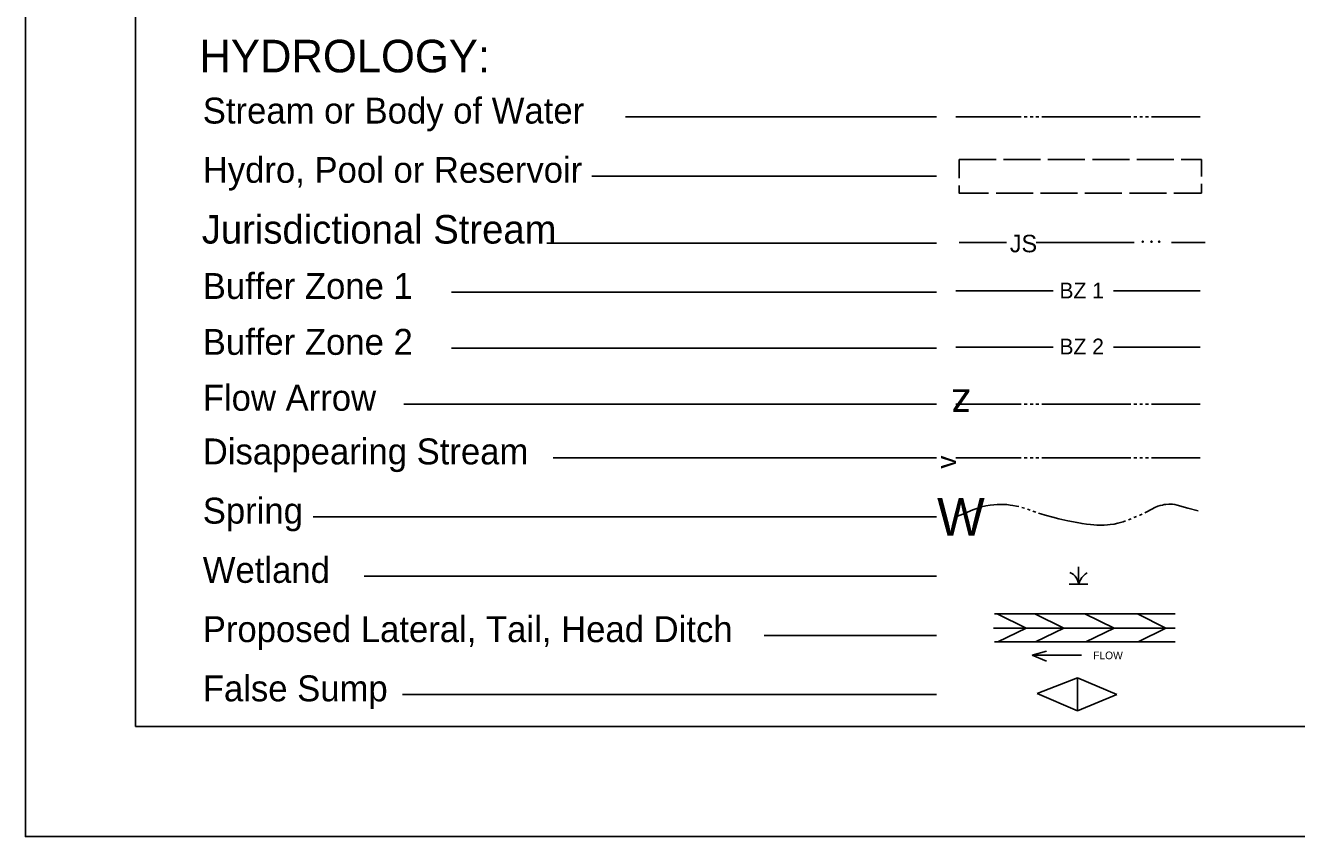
# Model space of a CAD drawing. Extents: x 1855058 to 1858918, y 1540202 to 1542502.
# Drawn here: x 1857118.6 to 1857551.6, y 1541401.8 to 1541678.1 of the extents above; entities that cross this region are included whole.
import ezdxf

# ---------------------------------------------------------------- set-up
doc = ezdxf.new("R2010")
doc.units = 0
for name, color, linetype in [('Default', 7, 'Continuous'), ('Exist Contamination Potential Cell', 7, 'Continuous'), ('Sheet Data Field CELL', 7, 'Continuous'), ('Sheet Symbology CELL', 7, 'Continuous')]:
    doc.layers.add(name, color=color, linetype=linetype)

msp = doc.modelspace()

# ---------------------------------------------------------------- linework, layer by layer
at = {"layer": 'Default'}
msp.add_lwpolyline([(1857118.6, 1542501.77), (1857118.6, 1541401.77), (1858818.6, 1541401.77), (1858818.6, 1542501.77)], close=True, dxfattribs=at)
at = {"layer": 'Exist Contamination Potential Cell'}
for p, q in [((1857118.6, 1542501.77), (1857118.6, 1541401.77)), ((1857118.6, 1541401.77), (1858818.6, 1541401.77))]:
    msp.add_line(p, q, dxfattribs=at)
at = {"layer": 'Sheet Data Field CELL'}
for p, q in [((1857428.97, 1541646.94), (1857323.03, 1541646.94)), ((1857435.54, 1541646.94), (1857457.76, 1541646.94)), ((1857458.77, 1541646.94), (1857459.78, 1541646.94)), ((1857460.78, 1541646.94), (1857461.79, 1541646.94)), ((1857462.8, 1541646.94), (1857463.81, 1541646.94)), ((1857464.82, 1541646.94), (1857495.09, 1541646.94)), ((1857496.1, 1541646.94), (1857497.11, 1541646.94)), ((1857498.12, 1541646.94), (1857499.12, 1541646.94)), ((1857500.13, 1541646.94), (1857501.14, 1541646.94)), ((1857502.15, 1541646.94), (1857518.77, 1541646.94)), ((1857436.61, 1541632.39), (1857449.22, 1541632.39)), ((1857436.61, 1541626.03), (1857436.61, 1541632.39)), ((1857451.74, 1541632.39), (1857464.35, 1541632.39)), ((1857466.88, 1541632.39), (1857479.49, 1541632.39)), ((1857482.01, 1541632.39), (1857494.62, 1541632.39)), ((1857497.14, 1541632.39), (1857509.76, 1541632.39)), ((1857428.97, 1541626.76), (1857311.54, 1541626.76)), ((1857461.81, 1541620.96), (1857449.19, 1541620.96)), ((1857476.94, 1541620.96), (1857464.33, 1541620.96)), ((1857492.07, 1541620.96), (1857479.46, 1541620.96)), ((1857507.21, 1541620.96), (1857494.6, 1541620.96)), ((1857428.97, 1541603.96), (1857296.18, 1541603.96)), ((1857428.97, 1541587.2), (1857263.75, 1541587.2)), ((1857435.54, 1541587.64), (1857468.62, 1541587.64)), ((1857518.77, 1541587.64), (1857489.21, 1541587.64)), ((1857428.97, 1541568.16), (1857263.75, 1541568.16)), ((1857435.54, 1541568.49), (1857468.62, 1541568.49)), ((1857518.77, 1541568.49), (1857489.21, 1541568.49)), ((1857428.97, 1541549.12), (1857247.52, 1541549.12)), ((1857435.54, 1541549.12), (1857457.76, 1541549.12)), ((1857458.77, 1541549.12), (1857459.78, 1541549.12)), ((1857460.78, 1541549.12), (1857461.79, 1541549.12)), ((1857462.8, 1541549.12), (1857463.81, 1541549.12)), ((1857464.82, 1541549.12), (1857495.09, 1541549.12)), ((1857496.1, 1541549.12), (1857497.11, 1541549.12)), ((1857498.12, 1541549.12), (1857499.12, 1541549.12)), ((1857500.13, 1541549.12), (1857501.14, 1541549.12)), ((1857502.15, 1541549.12), (1857518.77, 1541549.12)), ((1857428.97, 1541530.84), (1857298.3, 1541530.84)), ((1857435.54, 1541530.84), (1857457.76, 1541530.84)), ((1857458.77, 1541530.84), (1857459.78, 1541530.84)), ((1857460.78, 1541530.84), (1857461.79, 1541530.84)), ((1857462.8, 1541530.84), (1857463.81, 1541530.84)), ((1857464.82, 1541530.84), (1857495.09, 1541530.84)), ((1857496.1, 1541530.84), (1857497.11, 1541530.84)), ((1857498.12, 1541530.84), (1857499.12, 1541530.84)), ((1857500.13, 1541530.84), (1857501.14, 1541530.84)), ((1857502.15, 1541530.84), (1857518.77, 1541530.84)), ((1857428.97, 1541510.66), (1857216.61, 1541510.66)), ((1857461.78, 1541512.63), (1857462.74, 1541512.3)), ((1857494.27, 1541509.68), (1857495.2, 1541510.06)), ((1857496.15, 1541510.42), (1857497.07, 1541510.81)), ((1857477.27, 1541487.75), (1857477.27, 1541493.67)), ((1857428.97, 1541490.48), (1857234.03, 1541490.48)), ((1857474.08, 1541487.75), (1857480.51, 1541487.75)), ((1857448.63, 1541477.62), (1857510.18, 1541477.62)), ((1857449.54, 1541477.62), (1857459.41, 1541472.78)), ((1857462.36, 1541477.62), (1857472.24, 1541472.78)), ((1857479.46, 1541477.62), (1857489.38, 1541472.78)), ((1857497.36, 1541477.62), (1857507.04, 1541472.78)), ((1857428.97, 1541470.31), (1857370.27, 1541470.31)), ((1857448.36, 1541472.78), (1857510.18, 1541472.78)), ((1857459.41, 1541472.78), (1857449.81, 1541468.09)), ((1857472.24, 1541472.78), (1857462.68, 1541468.09)), ((1857489.38, 1541472.78), (1857479.82, 1541468.09)), ((1857507.04, 1541472.78), (1857497.62, 1541468.09)), ((1857448.63, 1541468.09), (1857510.18, 1541468.09)), ((1857461.49, 1541463.55), (1857466.33, 1541464.91)), ((1857461.49, 1541463.55), (1857478.29, 1541463.55)), ((1857461.49, 1541463.55), (1857466.33, 1541461.58)), ((1857476.94, 1541455.79), (1857463.24, 1541450.47)), ((1857476.94, 1541444.64), (1857476.94, 1541455.79)), ((1857490.37, 1541450.21), (1857476.94, 1541455.79)), ((1857428.97, 1541450.13), (1857247.08, 1541450.13)), ((1857463.24, 1541450.47), (1857476.94, 1541444.64)), ((1857476.94, 1541444.64), (1857490.37, 1541450.21))]:
    msp.add_line(p, q, dxfattribs=at)
for points in [[(1857512.28, 1541632.39), (1857519.16, 1541632.39), (1857519.16, 1541626.66)], [(1857446.67, 1541620.96), (1857436.61, 1541620.96), (1857436.61, 1541623.51)], [(1857519.16, 1541624.14), (1857519.16, 1541620.96), (1857509.73, 1541620.96)], [(1857436.61, 1541604.16), (1857452.76, 1541604.16)], [(1857462.89, 1541604.16), (1857477.03, 1541604.16)], [(1857477.03, 1541604.16), (1857496.2, 1541604.16)], [(1857508.91, 1541604.16), (1857520.43, 1541604.16)], [(1857435.55, 1541510.66), (1857438.41, 1541511.86), (1857441.29, 1541513.07), (1857442.01, 1541513.35), (1857443.28, 1541513.79), (1857444.26, 1541514.06), (1857445.74, 1541514.4), (1857447.23, 1541514.66), (1857448.48, 1541514.81), (1857449.59, 1541514.9), (1857450.56, 1541514.93), (1857451.41, 1541514.93), (1857452.91, 1541514.84), (1857454.04, 1541514.72), (1857454.87, 1541514.6), (1857456.12, 1541514.36), (1857456.98, 1541514.16)], [(1857457.96, 1541513.89), (1857458.43, 1541513.75), (1857458.92, 1541513.6)], [(1857459.88, 1541513.29), (1857460.29, 1541513.15), (1857460.84, 1541512.96)], [(1857499.83, 1541512.08), (1857500.31, 1541512.31), (1857502.29, 1541513.35), (1857503.3, 1541513.84), (1857504.35, 1541514.27), (1857505.14, 1541514.53), (1857505.85, 1541514.71), (1857506.48, 1541514.84), (1857507.03, 1541514.93), (1857508.02, 1541514.99), (1857508.75, 1541514.99), (1857509.29, 1541514.95), (1857510.1, 1541514.84), (1857510.89, 1541514.66), (1857514.47, 1541513.68), (1857518.04, 1541512.68)], [(1857463.7, 1541511.97), (1857464.47, 1541511.71), (1857465.88, 1541511.29), (1857468.59, 1541510.57), (1857470.63, 1541510.06), (1857473.7, 1541509.35), (1857476.79, 1541508.71), (1857478.5, 1541508.41), (1857480.02, 1541508.18), (1857481.35, 1541508.03), (1857482.53, 1541507.93), (1857483.55, 1541507.88), (1857484.46, 1541507.85), (1857486.02, 1541507.88), (1857487.19, 1541507.95), (1857488.08, 1541508.05), (1857489.38, 1541508.24), (1857490.66, 1541508.52), (1857491.63, 1541508.78), (1857492.48, 1541509.04), (1857493.32, 1541509.34)], [(1857498, 1541511.21), (1857498.2, 1541511.29), (1857498.92, 1541511.62)], [(1857477.27, 1541487.75), (1857477.12, 1541488.46), (1857476.91, 1541489.17), (1857476.56, 1541489.83), (1857476.1, 1541490.43), (1857475.6, 1541490.99), (1857474.99, 1541491.4), (1857474.33, 1541491.75)], [(1857477.27, 1541487.75), (1857477.57, 1541488.51), (1857477.93, 1541489.27), (1857478.38, 1541489.98), (1857478.94, 1541490.59), (1857479.55, 1541491.14), (1857480.21, 1541491.65)]]:
    msp.add_lwpolyline(points, dxfattribs=at)
for centre in [(1857499.17, 1541604.44), (1857502.15, 1541604.44), (1857504.76, 1541604.44)]:
    msp.add_ellipse(centre, major_axis=(0, 0.199), ratio=0.938496, dxfattribs=at)
at = {"layer": 'Sheet Symbology CELL'}
for q in [(1857156.1, 1542464.27), (1858781.08, 1541439.27)]:
    msp.add_line((1857156.1, 1541439.27), q, dxfattribs=at)

# ---------------------------------------------------------------- texts
at = {"layer": 'Sheet Data Field CELL'}
for s, height, p in [('HYDROLOGY:', 11.098, (1857177.87, 1541662.1)), ('Stream or Body of Water', 8.8282, (1857179.01, 1541644.66)), ('Hydro, Pool or Reservoir', 8.8282, (1857179.01, 1541624.48)), ('Jurisdictional Stream', 9.7323, (1857178.68, 1541603.77)), ('JS', 5.958, (1857453.88, 1541600.81)), ('Buffer Zone 1', 8.8282, (1857179.01, 1541584.92)), ('BZ 1', 5.362, (1857470.79, 1541585.11)), ('Buffer Zone 2', 8.8282, (1857179.01, 1541565.88)), ('BZ 2', 5.362, (1857470.79, 1541566.03)), ('Flow Arrow', 8.828, (1857179.01, 1541546.84)), ('Disappearing Stream', 8.8282, (1857179.01, 1541528.56)), ('Spring', 8.828, (1857179.01, 1541508.38)), ('W', 12.86, (1857429.12, 1541504.23)), ('Wetland', 8.828, (1857179.01, 1541488.2)), ('Proposed Lateral, Tail, Head Ditch', 8.8282, (1857179.01, 1541468.02)), ('FLOW', 2.616, (1857482.26, 1541462.18)), ('False Sump', 8.828, (1857179.01, 1541447.84))]:
    msp.add_text(s, height=height, dxfattribs=at).set_placement(p)
for s, height, rotation, p in [('z', 10.09, 180, (1857440.59, 1541554.17)), ('v', 6.66, 89.7591, (1857435.54, 1541527.07))]:
    msp.add_text(s, height=height, rotation=rotation, dxfattribs=at).set_placement(p)

doc.saveas('drawing.dxf')
